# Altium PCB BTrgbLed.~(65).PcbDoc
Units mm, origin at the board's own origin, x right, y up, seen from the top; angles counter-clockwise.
Board outline 98.71 x 98.67 mm, 2 copper layers (Top Layer, Bottom Layer); 15 components, 12 nets, 66 pads, 7 vias.
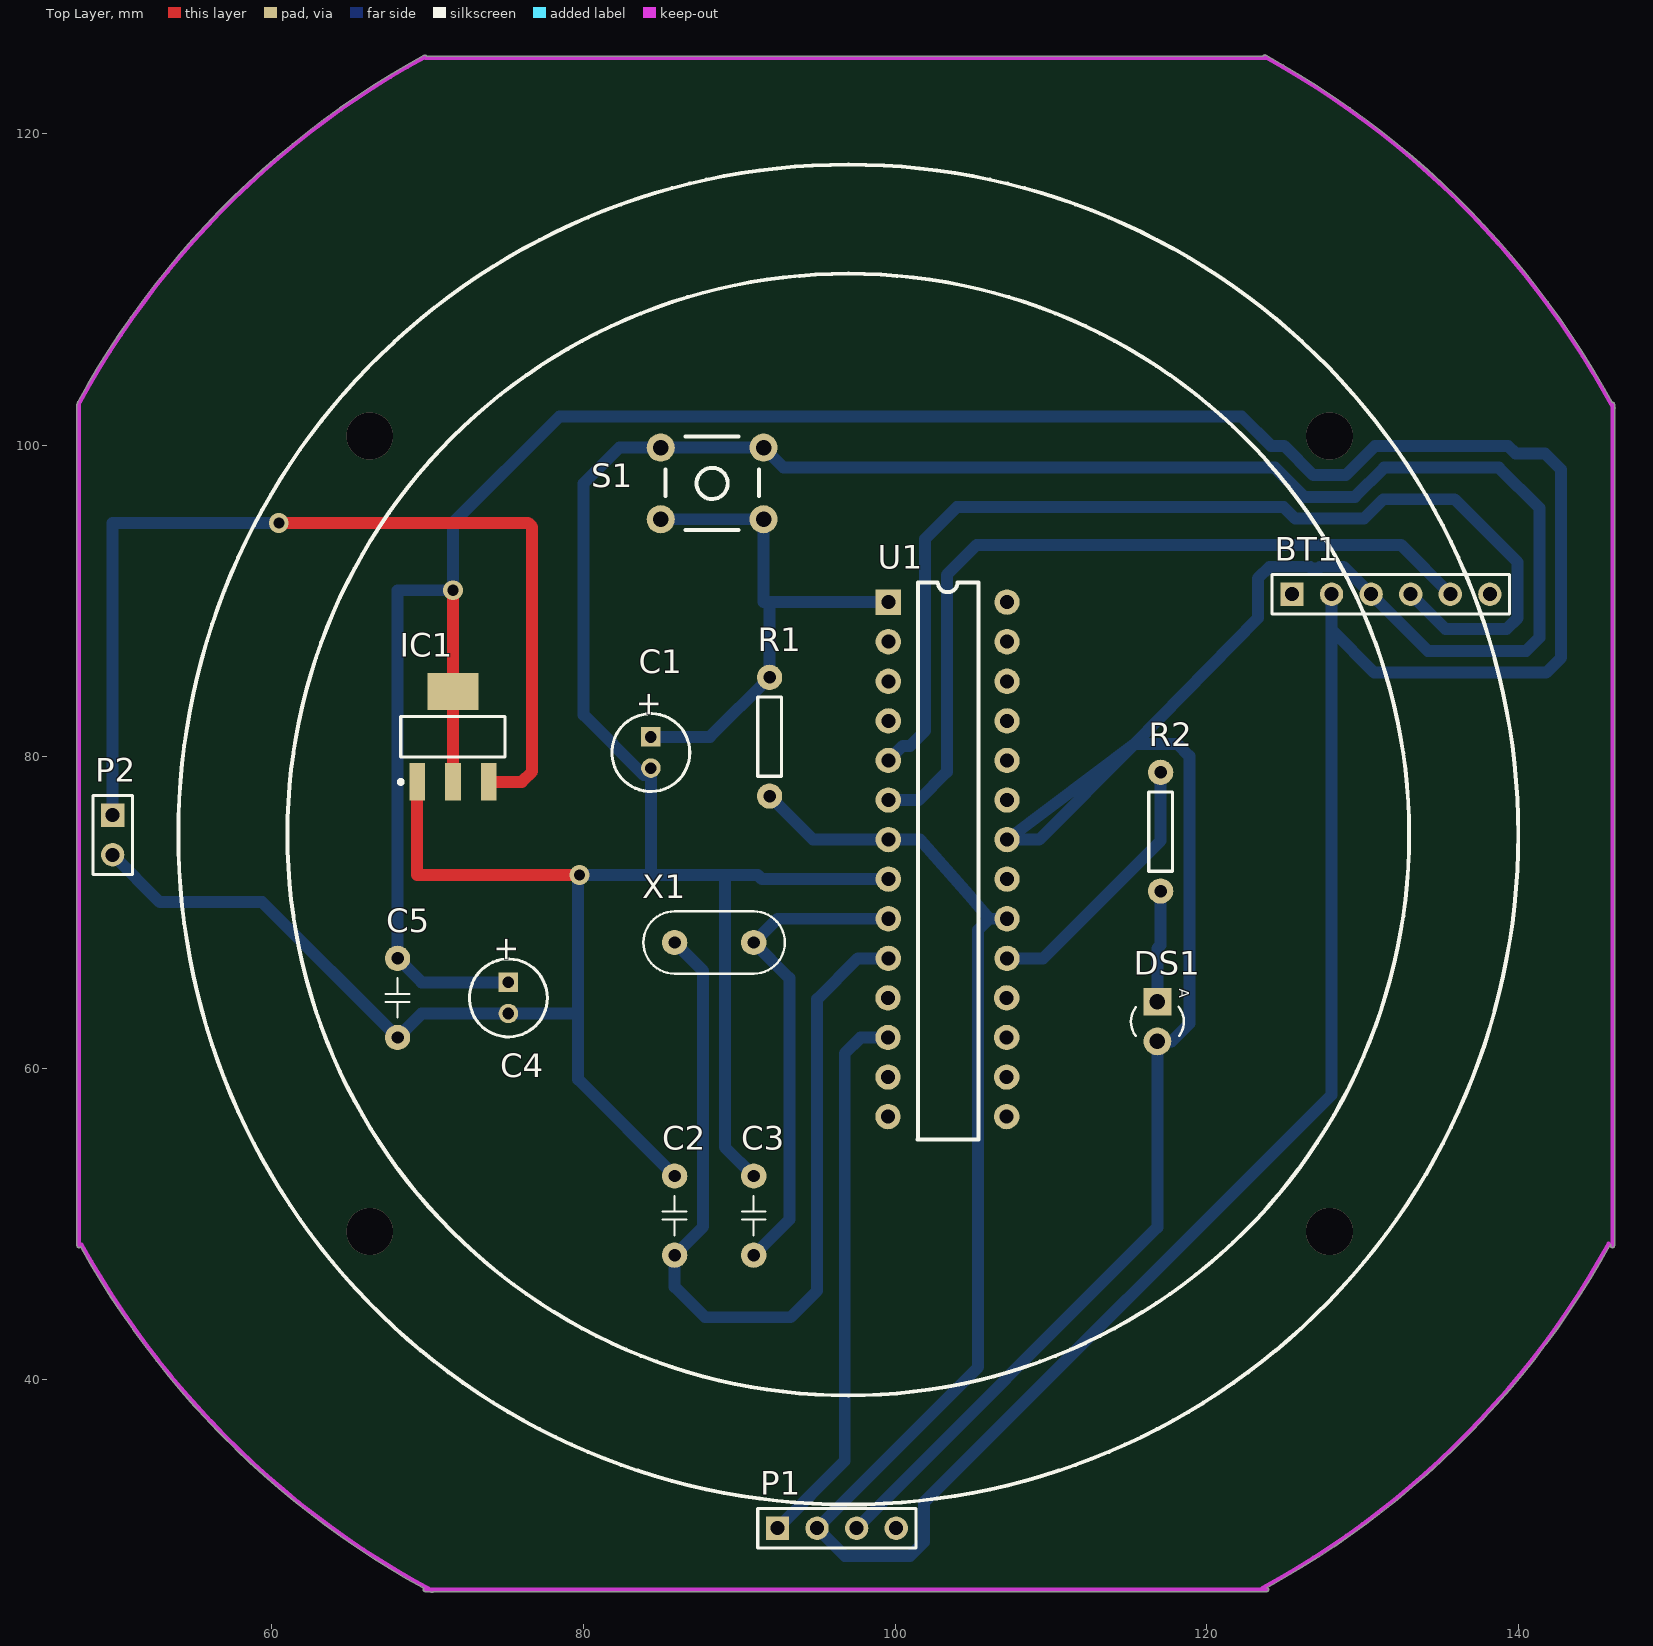
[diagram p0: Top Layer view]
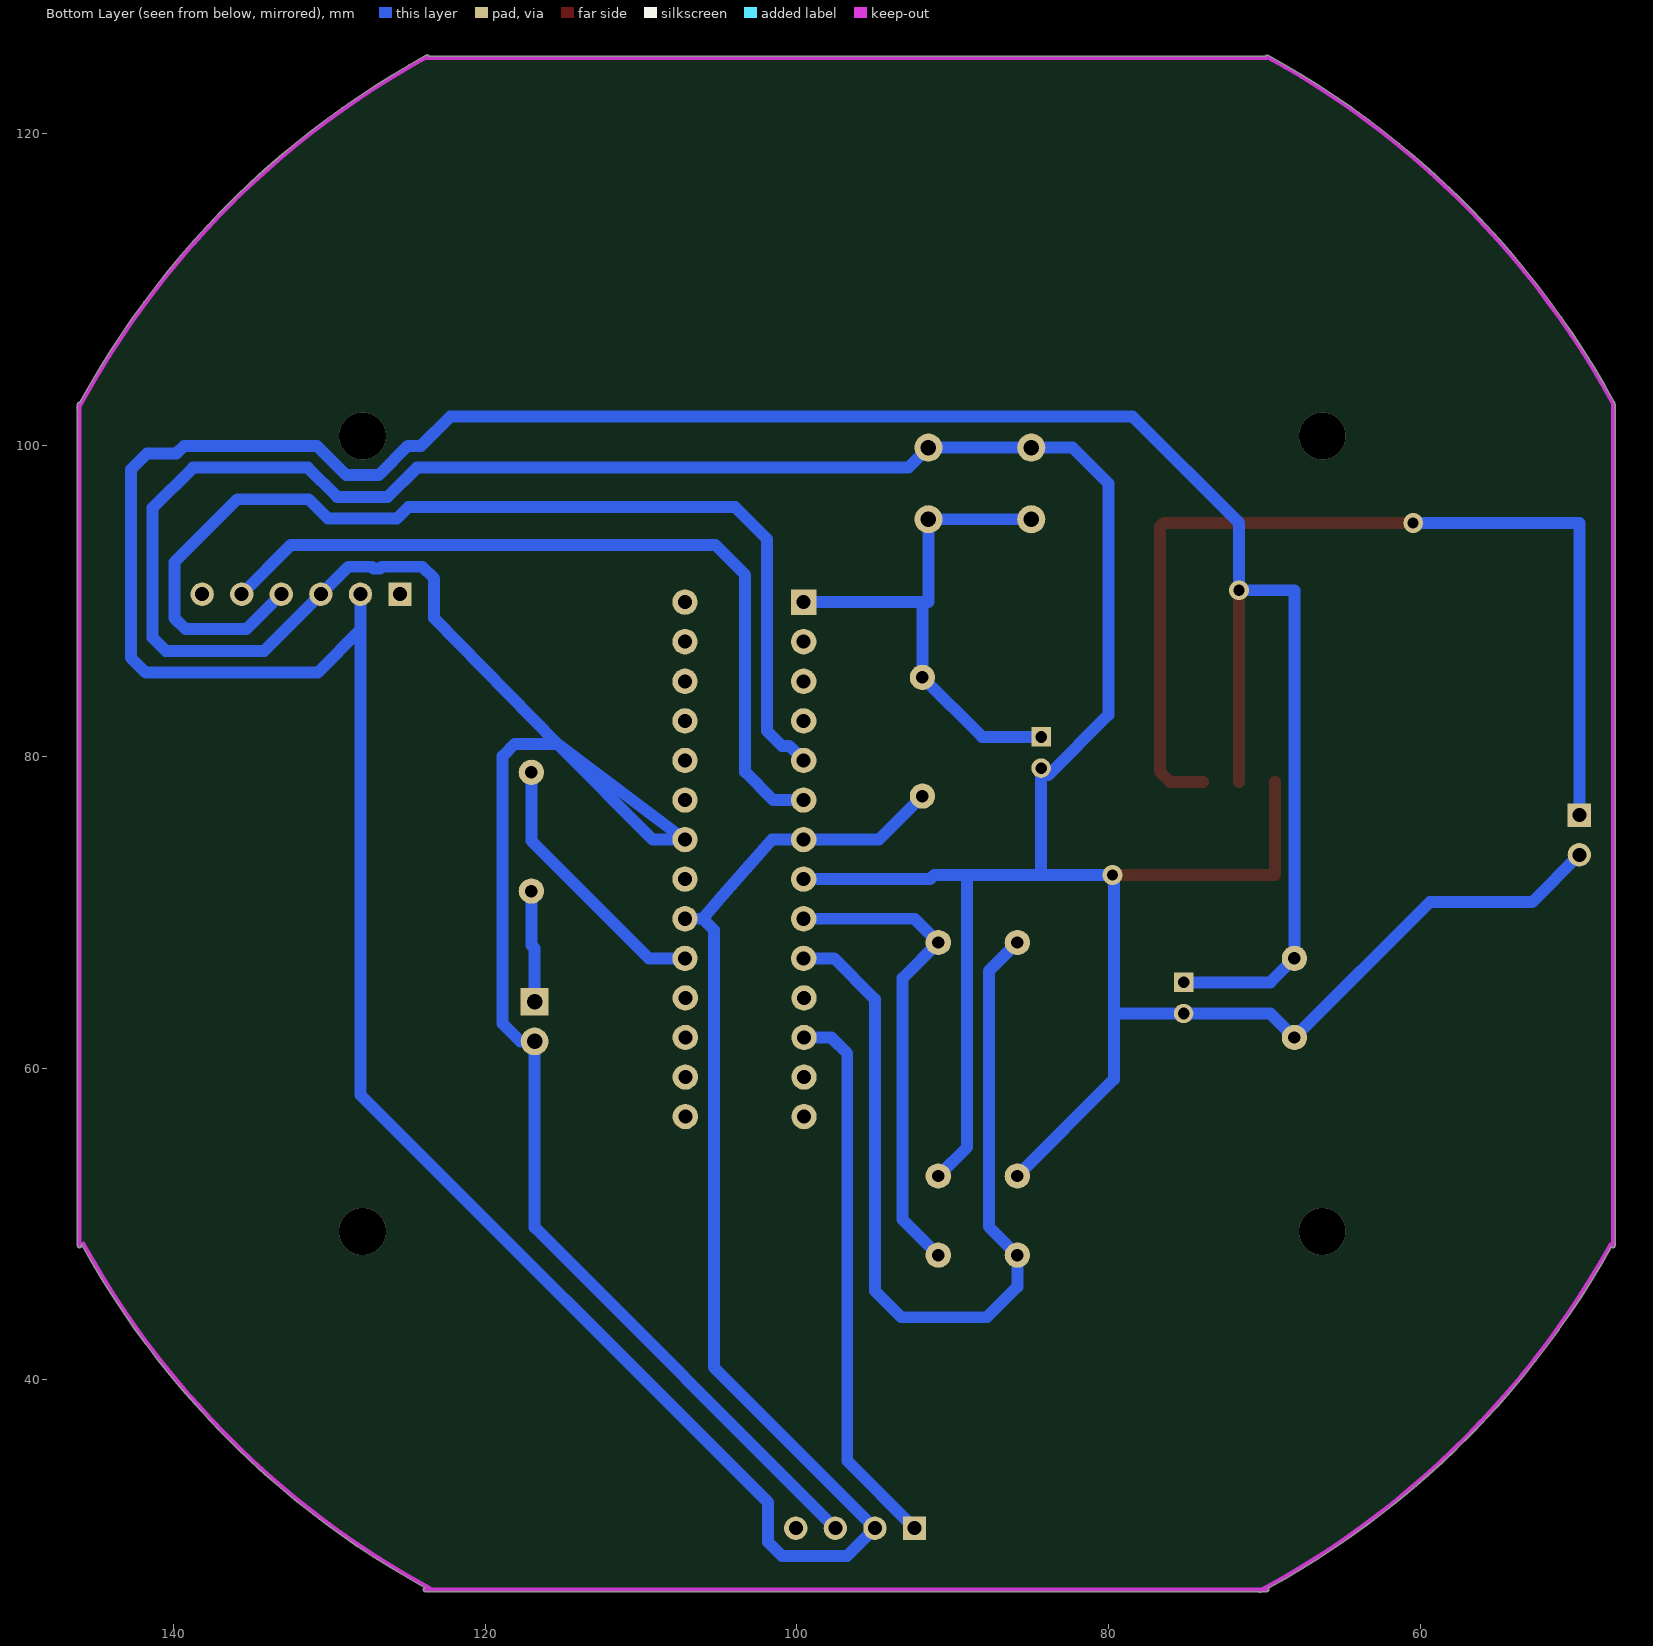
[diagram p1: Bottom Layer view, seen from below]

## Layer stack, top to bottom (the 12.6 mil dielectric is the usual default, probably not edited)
Top Layer: signal copper 0.0356
Dielectric: dielectric 0.32, FR-4, Dk 4.8
Bottom Layer: signal copper 0.0356

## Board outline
69.85,26.416 70.143,26.416 ccw(c96.781,75.819) 70.218,26.375 ccw(c70.279,26.487) 70.384,26.416 123.85,26.416 ccw(c123.85,26.543) 123.977,26.543 ccw(c123.85,26.543) 123.88,26.667 ccw(c96.781,75.819) 145.916,48.69 ccw(c145.805,48.751) 145.923,48.703 145.923,48.616 ccw(c146.05,48.616) 146.177,48.616 146.177,102.295 ccw(c146.082,102.379) 146.209,102.379 ccw(c146.082,102.379) 146.194,102.44 ccw(c96.781,75.819) 146.177,102.47 146.177,102.616 ccw(c146.05,102.616) 146.03,102.742 ccw(c96.781,75.819) 123.795,125.018 ccw(c123.734,124.906) 123.623,124.968 69.925,124.968 ccw(c69.817,124.9) 69.756,125.012 ccw(c96.781,75.819) 47.559,102.791 ccw(c47.671,102.73) 47.544,102.715 ccw(c47.625,102.616) 47.498,102.616 47.498,48.616 ccw(c47.625,48.616) 47.728,48.541 ccw(c96.781,75.819) 69.754,26.627 ccw(c69.85,26.543)

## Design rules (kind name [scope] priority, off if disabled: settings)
Clearance 舖銅安全間距 [All] p1: gap=0.635
Clearance [All] p2: gap=0.254
PolygonConnect [All] p1: connectstyle=Relief reliefconductorwidth=0.254 reliefentries=4 polygonreliefangle="90 Angle"
RoutingLayers [All] p1: top layer_v5=FALSE bottom layer_v5=TRUE
RoutingVias [All] p1: holewidth=0.711 width=1.27 viastyle="Through Hole" minholewidth=0.711 minwidth=1.27 maxholewidth=0.711 maxwidth=1.27
SilkscreenOverComponentPads [All] p1: minsilkscreentomaskgap=0.254
SolderMaskExpansion [All] p1: expansion=0.102
Width [All] p1: maxlimit=1.016 minlimit=0.508 preferedwidth=0.762
26 further rules are at their usual default settings.

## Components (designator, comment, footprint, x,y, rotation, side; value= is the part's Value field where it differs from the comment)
BT1 "Bluetooth" Bluetooth 125.476,90.424 r0 top
C1 "47uF" CAPPR2-5x6.8 84.328,80.264 r270 top
C2 "22pF" C200 85.852,50.546 r0 top
C3 "22pF" C200 90.932,50.546 r0 top
C4 "47uF" CAPPR2-5x6.8 75.184,64.516 r270 top
C5 "100pF" C200 68.072,64.516 r180 top
DS1 "TX-LED" LED-3mm_G 116.84,62.992 r270 top
IC1 "AM1117-5V" SOT-223 71.628,81.28 r90 top
P1 "環形LED燈" HDR1X4 92.456,30.48 r0 top
P2 "12V" HDR1X2 49.784,76.243 r270 top
R1 "10k" AXIAL-0.3 91.948,81.28 r90 top
R2 "220" AXIAL-0.3 117.048,75.184 r90 top
S1 "SW-PB" TACK6 88.263,97.536 r0 top
U1 "ATmega328" DIP-28 99.568,89.916 r270 top
X1 "16MHz" XTAL4-8 88.392,68.072 r180 top

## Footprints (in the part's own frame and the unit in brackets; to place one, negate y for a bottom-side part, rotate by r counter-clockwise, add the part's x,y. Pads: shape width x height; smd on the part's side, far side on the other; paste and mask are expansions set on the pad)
AXIAL-0.3 [mil] "0.3\" Resistor; 2 Leads"
  round 64 hole 31.5: 1(-150,0) 2(150,0)
  silkscreen extent -100,-30 100,30, body extent -161,-39 165,39, height 86
Bluetooth [mm]
  rect 1.5x1.5 hole 0.9: 1(0,0)
  round 1.5 hole 0.9: 2(2.54,0) 3(5.08,0) 4(7.62,0) 5(10.16,0) 6(12.7,0)
  silkscreen extent -1.27,-1.27 13.97,1.27, body extent -1.25,-1.3 13.97,1.28, height 11
C200 [mil] "塑膠電容器"
  round 64 hole 31.5: 1(0,100) 2(0,-100)
  silkscreen extent -30,-50 30,50, body extent -41,-136 39,135, height 354
CAPPR2-5x6.8 [mm] "Capacitor, Electrolytic, Radial; Body 5 x 6.8 mm (Dia.xH typ); Pin Spacing 2 mm (typ)"
  rect 1.25x1.25 hole 0.75: 1(-1,0)
  round 1.25 hole 0.75: 2(1,0)
  silkscreen extent -2.5,-2.5 2.5,2.5
DIP-28 [mil]
  rect 64x64 hole 35.43: 1(0,0)
  round 64 hole 35.43: 2(100,0) 3(200,0) 4(300,0) 5(400,0) 6(500,0) 7(600,0) 8(700,0) 9(800,0) 10(900,0) 11(1000,-0.79) 12(1100,-0.79) 13(1200,-0.79) 14(1300,-0.79) 15(1300,299.21) 16(1200,299.21) 17(1100,299.21) 18(1000,299.21) 19(900,300) 20(800,300) 21(700,300) 22(600,300) 23(500,300) 24(400,300) 25(300,300) 26(200,300) 27(100,300) 28(0,300)
  silkscreen extent -50,74 1358,228, body extent -53,-5 1358,304, height 209
HDR1X2 [mm] "Connector; Header; 2 Position"
  rect 1.5x1.5 hole 0.9: 1(0,0)
  round 1.5 hole 0.9: 2(2.54,0)
  silkscreen extent -1.27,-1.27 3.81,1.27
HDR1X4 [mm] "Connector; Header; 4 Position"
  rect 1.5x1.5 hole 0.9: 1(0,0)
  round 1.5 hole 0.9: 2(2.54,0) 3(5.08,0) 4(7.62,0)
  silkscreen extent -1.27,-1.27 8.89,1.27
LED-3mm_G [mil] "3mm LED_Green"
  rect 70x70 hole 39: 1(-50,0)
  round 70 hole 39: 2(50,0)
  silkscreen extent -38,-67 35,67, body extent -66,-68 67,66, height 181
SOT-223 [mm] "SOT223, 4-Leads, Body 6.7x7.3mm (max), Pitch 2.30mm, IPC Medium Density"
  rect 2.4x1 smd: 1(-2.9,2.3) 2(-2.9,0) 3(-2.9,-2.3)
  rect 2.4x3.3 smd: 2(2.9,0)
  silkscreen extent -3.02,-3.35 1.3,3.47, body extent -1.86,-3.35 1.86,3.35, height 1.8
TACK6 [mm]
  round 1.8 hole 1: 1(-3.3,2.3) 1(3.3,2.3) 2(-3.3,-2.3) 2(3.3,-2.3)
  silkscreen extent -3,-3 3,3, body extent -3,-3.01 3.08,3.04, height 8
XTAL4-8 [mil]
  round 64 hole 31.5: 1(-100,0) 2(100,0)
  silkscreen extent -179,-79 179,79, body extent -178,-80 192,79, height 157

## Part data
C1 C4: library part "Cap Pol1", "Polarized Capacitor (Radial)"
C2 C3 C5: library part Cap, "Capacitor"
DS1: library part LED, "Typical INFRARED GaAs LED"
IC1: library part AM1117
P1: library part "Header 4", "Header, 4-Pin"
P2: library part "Header 2", "Header, 2-Pin"
R1 R2: library part Res, "Resistor"
S1: "Switch"
U1: "Arduino"
X1: library part XTAL, "Crystal Oscillator"

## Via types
v1: diameter 3, hole 3, Top Layer to Bottom Layer, 4 vias
v2: diameter 1.27, hole 0.711, Top Layer to Bottom Layer, 3 vias

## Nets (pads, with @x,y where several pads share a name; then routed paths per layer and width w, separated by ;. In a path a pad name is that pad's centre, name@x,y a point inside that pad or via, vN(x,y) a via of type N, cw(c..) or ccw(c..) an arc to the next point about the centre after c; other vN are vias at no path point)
DI: P1.1 U1.12 | length 35.5
  Bottom Layer w0.762: P1.1 96.774,34.798 96.774,60.96 97.79,61.976 U1.12
DO: P1.4
GND: BT1.3 C1.2 C2.1 C3.1 C4.2 C5.1 DS1.2 IC1.1 P1.3 P2.2 S1.1 U1.8 U1.22 | length 333.6
  Top Layer w0.762: IC1.1 69.328,72.404 v2(79.742,72.404)
  Bottom Layer w0.762: P2.2 52.824,70.663 59.385,70.663 C5.1 69.612,63.516 C4.2 79.654,63.516 ; v2@79.654,72.404 79.654,63.516 ; v2(79.742,72.404) 91.188,72.404 91.456,72.136 U1.8 ; 84.328,72.658 C1.2 83.875,78.812 80.01,82.677 80.01,97.536 82.31,99.836 91.563,99.836 92.847,98.552 124.387,98.552 126.268,96.671 129.51,96.671 131.391,98.552 138.76,98.552 141.351,95.961 141.351,87.63 140.513,86.792 134.188,86.792 BT1.3 128.79,92.19 127.285,92.19 127.169,92.075 126.762,92.075 126.647,92.19 124.042,92.19 123.292,91.44 123.292,88.9 115.392,80.823 ; C2.1 79.654,59.284 79.654,63.516 ; 89.154,72.302 89.078,72.226 89.078,54.94 C3.1 ; P1.3 116.84,49.784 DS1.2 117.754,61.722 118.897,62.865 118.897,80.035 118.11,80.823 115.392,80.823 ; 115.392,80.823 U1.22 109.245,74.676 115.392,80.823
NetC1_1: C1.1 R1.2 S1.2 U1.1 | length 33.7
  Bottom Layer w0.762: C1.1 88.122,81.264 R1.2 91.948,89.662 ; S1.2@84.963,95.236 91.563,95.236 91.563,89.916 U1.1
NetC2_2: C2.2 U1.10 X1.2 | length 58.6
  Bottom Layer w0.762: X1.2 87.681,66.243 87.681,49.835 C2.2 85.852,45.974 87.808,44.018 93.294,44.018 94.996,45.72 94.996,64.44 97.612,67.056 U1.10
NetC3_2: C3.2 U1.9 X1.1 | length 31.2
  Bottom Layer w0.762: C3.2 93.218,50.292 93.218,65.786 X1.1 92.456,69.596 U1.9
NetDS1_1: DS1.1 R2.1 | length 7.2
  Bottom Layer w0.762: DS1.1 116.84,67.691 117.048,67.899 R2.1
NetIC1_3: IC1.3 P2.1 | length 64.6
  Top Layer w0.762: v2@60.706,94.996 76.454,94.996 76.708,94.742 76.708,79.036 76.052,78.38 IC1.3
  Bottom Layer w0.762: P2.1@50.081,76.243 P2.1 49.784,94.996 v2(60.452,94.996)
NetR2_2: R2.2 U1.19 | length 17.4
  Bottom Layer w0.762: U1.19 109.499,67.056 117.048,74.604 R2.2
RX: BT1.5 U1.6 | length 51.6
  Bottom Layer w0.762: U1.6 101.524,77.216 103.327,79.019 103.327,91.669 105.246,93.587 132.473,93.587 BT1.5
TX: BT1.4 U1.5 | length 68.5
  Bottom Layer w0.762: U1.5 100.508,80.696 100.965,80.696 101.93,81.661 101.93,93.98 103.962,96.012 124.952,96.012 125.69,95.274 130.088,95.274 131.334,96.52 135.914,96.52 139.954,92.48 139.954,88.9 139.243,88.189 135.331,88.189 BT1.4
VCC: BT1.2 C4.1 C5.2 IC1.2 P1.2 R1.1 U1.7 U1.20 | length 298.8
  Top Layer w0.762: IC1.2@71.628,78.38 71.628,84.18 v2(71.628,90.678)
  Bottom Layer w0.762: C4.1 69.612,65.516 C5.2 68.072,90.678 v2(71.628,90.678) 71.628,94.996 78.461,101.829 122.25,101.829 124.13,99.949 124.966,99.949 126.847,98.068 128.931,98.068 130.812,99.949 139.339,99.949 139.823,99.465 141.708,99.465 142.748,98.425 142.748,86.36 141.783,85.395 130.759,85.395 128.016,88.138 ; R1.1 94.742,74.676 U1.7 101.6,74.676 104.75,71.12 106.045,69.596 ; U1.20 106.045,69.596 ; BT1.2 128.016,88.138 ; 106.045,69.596 105.334,68.885 105.334,40.818 P1.2 96.774,28.702 100.965,28.702 101.854,29.591 101.854,32.131 128.016,58.293 128.016,88.138
pads on no net: BT1.1 BT1.6 U1.2 U1.3 U1.4 U1.11 U1.13 U1.14 U1.15 U1.16 U1.17 U1.18 U1.21 U1.23 U1.24 U1.25 U1.26 U1.27 U1.28
copper on no net:
  other v1: 66.294,49.53 127.889,49.53 66.294,100.584 127.889,100.584

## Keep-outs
Keep-Out Layer:
  lines w0.254: 47.625,48.616 47.625,102.616 ; 47.671,102.73 cw(c96.781,75.819) 69.817,124.9 ; 47.783,48.704 ccw(c96.781,75.819) 70.279,26.487 ; 69.85,26.543 123.85,26.543 ; 69.85,124.841 123.85,124.841 ; 123.584,26.65 ccw(c96.781,75.819) 145.805,48.751 ; 123.734,124.906 cw(c96.781,75.819) 146.082,102.379 ; 146.05,48.616 146.05,102.616

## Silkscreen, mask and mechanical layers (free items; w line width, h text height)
Top Overlay:
  circle w0.254: c97,75 r36
  circle w0.254: c97,75 r43
  rectangle: 171.196,41.454 186.196,76.454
